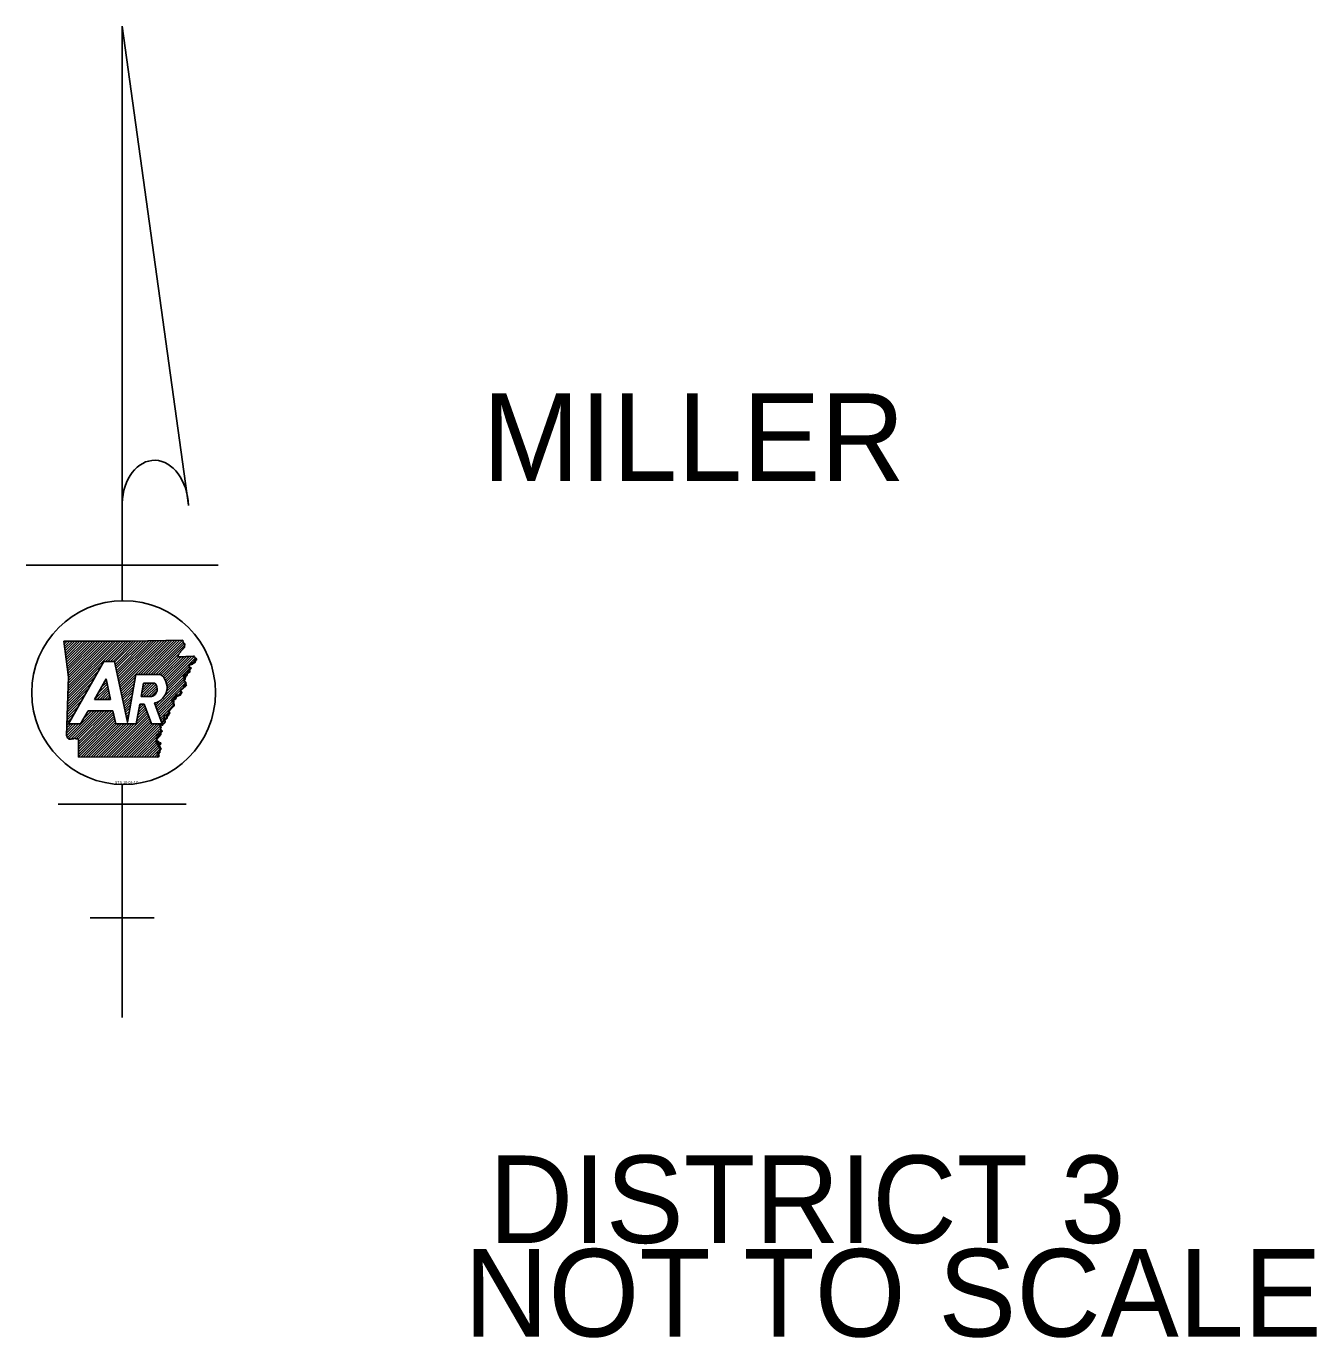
# Model space of a CAD drawing. Extents: x -35254 to 17396, y -8913 to 11592.
# Drawn here: x 11584 to 15125, y -5034 to -1436 of the extents above; entities that cross this region are included whole.
import ezdxf

# ---------------------------------------------------------------- set-up
doc = ezdxf.new("R2010")
doc.units = 0
doc.layers.add('2', color=7, linetype='Continuous')
doc.layers.add('R_Annotation', color=7, linetype='Continuous')

msp = doc.modelspace()

# ---------------------------------------------------------------- linework, layer by layer
at = {"layer": 'R_Annotation'}
for p, q in [((11847.3, -1436), (12029.1, -2750.1)), ((11847.3, -3011.9), (11847.3, -1436)), ((11584.1, -2914.4), (12110.4, -2914.4)), ((11687.6, -3124.7), (11689.8, -3122.6)), ((11688.4, -3130.9), (11696.8, -3122.6)), ((11689.2, -3137.1), (11703.7, -3122.6)), ((11689.9, -3143.3), (11710.7, -3122.6)), ((11690.7, -3149.5), (11717.6, -3122.6)), ((11691.5, -3155.7), (11724.6, -3122.6)), ((11692.3, -3161.9), (11731.6, -3122.6)), ((11693, -3168.1), (11738.5, -3122.6)), ((11693.8, -3174.3), (11745.5, -3122.6)), ((11694.6, -3180.5), (11752.5, -3122.6)), ((11695.3, -3186.7), (11759.4, -3122.6)), ((11696.1, -3192.9), (11766.4, -3122.6)), ((11696.9, -3199.1), (11773.3, -3122.6)), ((11697.7, -3205.3), (11780.3, -3122.6)), ((11697.9, -3274.7), (11850.1, -3122.5)), ((11698.1, -3267.5), (11843.1, -3122.5)), ((11698.4, -3260.3), (11836.1, -3122.5)), ((11698.4, -3211.5), (11787.3, -3122.6)), ((11698.6, -3253.1), (11829.2, -3122.5)), ((11698.8, -3245.9), (11822.2, -3122.5)), ((11699.1, -3238.7), (11815.2, -3122.6)), ((11699.2, -3217.7), (11794.3, -3122.6)), ((11699.3, -3231.5), (11808.2, -3122.6)), ((11699.6, -3224.3), (11801.2, -3122.6)), ((11801.3, -3178.2), (11857.1, -3122.5)), ((11808.3, -3178.2), (11864.1, -3122.5)), ((11815.3, -3178.2), (11871.1, -3122.4)), ((11822.2, -3178.2), (11878.2, -3122.3)), ((11826.6, -3180.8), (11885.2, -3122.2)), ((11827.8, -3186.6), (11892.3, -3122.1)), ((11829, -3192.3), (11899.4, -3122)), ((11830.3, -3198.1), (11906.5, -3121.9)), ((11831.5, -3203.8), (11913.5, -3121.7)), ((11832.7, -3209.5), (11920.6, -3121.6)), ((11833.9, -3215.3), (11927.7, -3121.5)), ((11835.2, -3221), (11934.8, -3121.4)), ((11836.4, -3226.7), (11941.8, -3121.3)), ((11837.6, -3232.5), (11948.9, -3121.2)), ((11838.8, -3238.2), (11956, -3121.1)), ((11840.1, -3244), (11963.1, -3121)), ((11841.3, -3249.7), (11970.2, -3120.8)), ((11842.5, -3255.4), (11977.3, -3120.7)), ((11890.9, -3214), (11984.4, -3120.5)), ((11897.9, -3214), (11991.6, -3120.3)), ((11904.9, -3214), (11998.7, -3120.2)), ((11911.8, -3214), (12005.8, -3120)), ((11918.8, -3214), (12012.9, -3119.8)), ((11925.7, -3214), (12014.5, -3125.3)), ((11932.7, -3214), (12017.9, -3128.9)), ((11939.7, -3214), (12018.8, -3134.9)), ((11946.6, -3214), (12002.9, -3157.8)), ((11956.8, -3217.8), (12008.8, -3165.8)), ((11960.2, -3221.4), (12016.2, -3165.4)), ((11963.2, -3225.3), (12023.5, -3165)), ((11965.8, -3229.7), (12030.9, -3164.6)), ((11967.9, -3234.6), (12038.2, -3164.2)), ((11969.5, -3239.9), (12044.8, -3164.6)), ((11697.7, -3281.9), (11791.6, -3187.9)), ((11700, -3349.8), (11797.1, -3178.2)), ((11797.1, -3178.2), (11826, -3178.2)), ((11953, -3214.6), (12001.5, -3166.1)), ((11969, -3261.3), (12032.3, -3198.1)), ((11970.4, -3245.9), (12048.1, -3168.3)), ((11970.5, -3252.9), (12031.5, -3191.9)), ((12045, -3178.4), (12051.3, -3172)), ((11696.9, -3303.5), (11764.4, -3236.1)), ((11697.2, -3296.3), (11773.5, -3220)), ((11697.4, -3289.1), (11782.6, -3204)), ((11771.4, -3282.5), (11803.2, -3226.3)), ((11789.2, -3251.1), (11805.1, -3235.2)), ((11798.3, -3235.1), (11803.9, -3229.5)), ((11843.8, -3261.2), (11883.3, -3221.6)), ((11845, -3266.9), (11881.8, -3230.1)), ((11884.6, -3214), (11952.1, -3214)), ((11940.3, -3304), (12017.5, -3226.8)), ((11942.2, -3309.1), (12018.8, -3232.4)), ((11963, -3274.3), (12016.2, -3221.1)), ((12024.5, -3212.8), (12033.1, -3204.2)), ((11696.5, -3317.9), (11746.2, -3268.2)), ((11696.7, -3310.7), (11755.3, -3252.1)), ((11771.8, -3282.5), (11807.6, -3246.7)), ((11778.7, -3282.5), (11808.8, -3252.4)), ((11780.1, -3267.2), (11806.3, -3240.9)), ((11785.7, -3282.5), (11810, -3258.1)), ((11792.7, -3282.5), (11811.3, -3263.9)), ((11799.6, -3282.5), (11812.5, -3269.6)), ((11846.2, -3272.6), (11880.3, -3238.5)), ((11847.4, -3278.4), (11878.9, -3247)), ((11848.7, -3284.1), (11877.4, -3255.4)), ((11849.9, -3289.9), (11875.9, -3263.8)), ((11851.1, -3295.6), (11874.5, -3272.3)), ((11899.3, -3274.9), (11935.9, -3238.2)), ((11900.7, -3266.5), (11929, -3238.2)), ((11902.2, -3258.1), (11922, -3238.2)), ((11903.7, -3249.6), (11915.1, -3238.2)), ((11905.1, -3241.2), (11908.1, -3238.2)), ((11905.6, -3238.2), (11937.3, -3238.2)), ((11906.3, -3274.9), (11939.8, -3241.3)), ((11913.2, -3274.9), (11942.2, -3245.9)), ((11920.2, -3274.9), (11943.5, -3251.6)), ((11927.2, -3274.9), (11942.9, -3259.2)), ((11944, -3314.1), (12020.1, -3238.1)), ((11945.9, -3319.2), (12021.4, -3243.7)), ((11997.6, -3274.5), (12007.4, -3264.7)), ((11696, -3332.3), (11728, -3300.3)), ((11696.2, -3325.1), (11737.1, -3284.3)), ((11771.4, -3282.5), (11815.2, -3282.5)), ((11806.6, -3282.5), (11813.7, -3275.4)), ((11813.6, -3282.5), (11814.9, -3281.1)), ((11852.4, -3301.3), (11873, -3280.7)), ((11853.6, -3307.1), (11871.5, -3289.1)), ((11854.8, -3312.8), (11870.1, -3297.6)), ((11856, -3318.6), (11868.6, -3306)), ((11890.3, -3326), (11911.1, -3305.3)), ((11891.8, -3317.6), (11909.2, -3300.2)), ((11893.3, -3309.2), (11907.2, -3295.2)), ((11894.8, -3300.7), (11900.2, -3295.2)), ((11907.4, -3295.2), (11895.7, -3295.2)), ((11899.3, -3274.9), (11928.2, -3274.9)), ((11927.6, -3349.8), (11907.4, -3295.2)), ((11936, -3292.3), (11957.2, -3349.8)), ((11936.5, -3293.8), (11938.6, -3291.7)), ((11938.4, -3298.9), (11951.6, -3285.6)), ((11947.8, -3324.3), (11989.6, -3282.5)), ((11949.7, -3329.4), (11988.8, -3290.3)), ((11951.5, -3334.5), (11988, -3298)), ((11695.5, -3346.7), (11709.8, -3332.4)), ((11695.7, -3339.5), (11718.9, -3316.4)), ((11697, -3387), (11770.2, -3313.8)), ((11701.1, -3389.8), (11777.2, -3313.8)), ((11706.2, -3391.8), (11784.2, -3313.8)), ((11714.4, -3390.5), (11791.1, -3313.8)), ((11721.5, -3390.4), (11798.1, -3313.8)), ((11727, -3391.9), (11805, -3313.8)), ((11727.2, -3405.6), (11819, -3313.8)), ((11727.2, -3398.6), (11812, -3313.8)), ((11727.2, -3412.5), (11822.6, -3317.1)), ((11727.2, -3419.5), (11823.9, -3322.8)), ((11727.3, -3426.4), (11825.1, -3328.6)), ((11727.3, -3433.4), (11826.3, -3334.3)), ((11727.4, -3440.2), (11827.6, -3340.1)), ((11753.7, -3313.8), (11733.3, -3349.8)), ((11734.4, -3440.2), (11828.8, -3345.8)), ((11741.2, -3335.9), (11763.3, -3313.8)), ((11750.3, -3319.8), (11756.3, -3313.8)), ((11821.9, -3313.8), (11753.7, -3313.8)), ((11796.9, -3440.3), (11916.7, -3320.5)), ((11803.9, -3440.4), (11918.6, -3325.6)), ((11810.8, -3440.4), (11920.5, -3330.7)), ((11817.8, -3440.4), (11922.4, -3335.8)), ((11824.8, -3440.4), (11924.3, -3340.9)), ((11857.3, -3324.3), (11867.1, -3314.4)), ((11858.5, -3330), (11865.6, -3322.9)), ((11859.7, -3335.8), (11864.2, -3331.3)), ((11860.9, -3341.5), (11862.7, -3339.7)), ((11887.4, -3342.9), (11914.9, -3315.4)), ((11888.9, -3334.5), (11913, -3310.4)), ((11953.4, -3339.6), (11974.8, -3318.2)), ((11955.3, -3344.7), (11971.8, -3328.2)), ((11694.4, -3382.7), (11727.2, -3349.8)), ((11694.5, -3375.6), (11720.3, -3349.8)), ((11694.8, -3368.4), (11713.3, -3349.8)), ((11695, -3361.1), (11706.3, -3349.8)), ((11695.3, -3353.9), (11700.7, -3348.5)), ((11733.3, -3349.8), (11700, -3349.8)), ((11741.3, -3440.2), (11831.7, -3349.8)), ((11748.3, -3440.3), (11838.7, -3349.8)), ((11755.2, -3440.3), (11845.7, -3349.8)), ((11762.2, -3440.3), (11852.6, -3349.8)), ((11769.1, -3440.3), (11859.6, -3349.8)), ((11776.1, -3440.3), (11866.6, -3349.8)), ((11783, -3440.3), (11873.5, -3349.8)), ((11790, -3440.3), (11880.5, -3349.8)), ((11886.2, -3349.8), (11829.6, -3349.8)), ((11831.7, -3440.4), (11926.1, -3346)), ((11838.7, -3440.4), (11929.3, -3349.8)), ((11845.6, -3440.4), (11936.2, -3349.8)), ((11852.6, -3440.4), (11943.2, -3349.8)), ((11859.5, -3440.4), (11950.2, -3349.8)), ((11866.5, -3440.5), (11952.5, -3354.5)), ((11873.4, -3440.5), (11952.8, -3361.1)), ((11880.4, -3440.5), (11953.1, -3367.8)), ((11887.3, -3440.5), (11953.4, -3374.4)), ((11957.2, -3349.8), (11927.6, -3349.8)), ((11894.3, -3440.5), (11942, -3392.8)), ((11901.3, -3440.5), (11944.1, -3397.6)), ((11908.2, -3440.5), (11946.3, -3402.5)), ((11915.2, -3440.5), (11948.4, -3407.3)), ((11922.1, -3440.5), (11950.6, -3412.1)), ((11929.1, -3440.6), (11952.4, -3417.3)), ((11936, -3440.6), (11949.2, -3427.4)), ((11943, -3440.6), (11946.1, -3437.5)), ((11847.3, -4155.5), (11847.3, -3516)), ((11671.8, -3570.3), (12022.7, -3570.3)), ((11759.5, -3881.9), (11935, -3881.9))]:
    msp.add_line(p, q, dxfattribs=at)
for points in [[(11687.3, -3122.6), (11783.4, -3122.6), (11867.8, -3122.4), (11967.3, -3120.9), (12013.4, -3119.8)], [(11698, -3272), (11699.7, -3221.3), (11687.3, -3122.6)], [(11687.4, -3122.6), (11783.5, -3122.6), (11867.8, -3122.5), (11967.3, -3120.9), (12013.4, -3119.8)], [(11694.3, -3382.6), (11699.7, -3221.3), (11687.4, -3122.6)], [(12043.6, -3164), (12051.9, -3172.7), (12031.2, -3189.7), (12033.4, -3206.9), (12015.6, -3218.6), (12021.7, -3245.1), (12008, -3257.6), (12006.8, -3271.2), (11990.1, -3277.2), (11987.5, -3302.9), (11975.5, -3315.7), (11969.8, -3335), (11952.3, -3351), (11953.6, -3379.1), (11941.8, -3392.4), (11952.6, -3416.6), (11945.1, -3440.6)], [(11999.1, -3166.2), (12044.2, -3163.9)], [(11999.1, -3166.3), (12044.2, -3163.9)], [(11826, -3178.2), (11861.7, -3345.2), (11884.6, -3214)], [(11803.2, -3226.3), (11815.2, -3282.5)], [(11694.3, -3382.6), (11698, -3272)], [(11899.3, -3274.9), (11905.6, -3238.2)], [(11895.7, -3295.2), (11886.2, -3349.8)], [(11829.6, -3349.8), (11821.9, -3313.8)], [(11945.1, -3440.6), (11727.3, -3440.2), (11727.2, -3392.1)], [(11945.1, -3440.6), (11727.3, -3440.2), (11727.2, -3392.1)]]:
    msp.add_lwpolyline(points, dxfattribs=at)
for centre, major_axis, ratio, start_param, end_param in [((11938.1, -2753), (-3.9, 126.3), 0.719778, 4.712385, 7.768526), ((11927, -3249.7), (-43.6, 0), 0.999987, 1.777838, 4.099264), ((11921.3, -3253.7), (-22.3, 0), 0.999987, 1.887169, 3.90762)]:
    msp.add_ellipse(centre, major_axis=major_axis, ratio=ratio, start_param=start_param, end_param=end_param, dxfattribs=at)
msp.add_ellipse((11851.4, -3263.9), major_axis=(252.1, 0), ratio=0.999976, dxfattribs=at)
for points in [[(12013.4, -3119.8), (12013.7, -3122.4), (12014.5, -3123.8), (12014.6, -3126.3), (12015.7, -3127.4), (12017.4, -3128.5), (12018.9, -3130.2), (12019.3, -3132.2), (12018.8, -3134.3), (12018.7, -3136.6), (12018.5, -3138.6), (12018.1, -3140.4), (12016.7, -3142), (12015.3, -3143), (12014.1, -3144.2), (12013.2, -3145.6), (12011.6, -3147), (12010.1, -3148.5), (12008.8, -3149.8), (12007.6, -3151.5), (12007, -3153.3), (12005.6, -3154.6), (12004.5, -3155.8), (12003.1, -3157.4), (12002.4, -3159), (12001.1, -3160.8), (12000.7, -3162.6), (11999.9, -3164), (11999.8, -3164.3)], [(12013.4, -3119.8), (12013.7, -3122.5), (12014.5, -3123.8), (12014.6, -3126.3), (12015.7, -3127.4), (12017.4, -3128.5), (12018.9, -3130.2), (12019.3, -3132.2), (12018.8, -3134.3), (12018.7, -3136.6), (12018.4, -3138.6), (12018.1, -3140.5), (12016.7, -3141.9), (12015.3, -3143), (12014, -3144.3), (12013.2, -3145.6), (12011.6, -3147), (12010.1, -3148.5), (12008.8, -3149.8), (12007.6, -3151.5), (12007, -3153.3), (12005.6, -3154.6), (12004.5, -3155.8), (12003.1, -3157.4), (12002.4, -3159), (12001, -3160.8), (12000.7, -3162.6), (11999.8, -3164.1), (11999.8, -3164.3)], [(12043.6, -3164), (12044.2, -3163.9), (12046.2, -3166.1), (12047.1, -3167.9), (12048.5, -3168.9), (12050, -3169.4), (12051.1, -3170.8), (12051.8, -3172.3), (12051.4, -3173.6), (12049.7, -3173.7), (12047.9, -3174), (12046.1, -3173.9), (12044.7, -3175.1), (12046, -3176.7), (12047.7, -3178.2), (12048.2, -3179.8), (12047.3, -3181.3), (12045.4, -3182.2), (12043.5, -3182.9), (12041.9, -3184.3), (12041.1, -3185.7), (12039.2, -3186.3), (12037.3, -3186.8), (12035.7, -3187), (12033.8, -3187.4), (12032, -3188.3), (12031.2, -3189.8), (12031.4, -3192), (12031.4, -3194.3), (12033.3, -3195.1), (12035, -3195.2), (12036.7, -3196), (12036.5, -3197.3), (12035.3, -3199), (12033.8, -3200.3), (12032.3, -3200.9), (12030.9, -3202.2), (12031.4, -3203.5), (12032.6, -3204.3), (12033.5, -3205.6), (12033.4, -3206.9), (12032, -3207.8), (12030.4, -3207.4), (12029.3, -3205.9), (12028, -3205.5), (12026.9, -3204.9), (12025.6, -3205.7), (12025.6, -3207.4), (12025.1, -3209.3), (12025.5, -3210.6), (12026, -3212.5), (12026, -3214), (12025.5, -3216), (12024.5, -3218.1), (12023.4, -3218.7), (12022.8, -3216.5), (12022.6, -3214.6), (12021.9, -3213.5), (12020.9, -3213.5), (12019.7, -3214.4), (12018.3, -3215.8), (12016.6, -3217.3), (12015.6, -3218.7), (12016.1, -3220.6), (12017.4, -3221), (12018.5, -3220.7), (12019, -3219.5), (12019.9, -3219.3), (12020.9, -3221.2)], [(12020.9, -3221.2), (12021.2, -3222.9), (12020.2, -3224.7), (12019.8, -3226.5), (12019.9, -3228.4), (12018.1, -3229.4), (12016.4, -3230.6), (12017.4, -3232), (12019.2, -3233.3), (12020.9, -3234.3), (12022, -3235.4), (12022.3, -3237.8), (12022.7, -3239.4), (12023.3, -3241.5), (12023.5, -3243), (12022.4, -3244.7), (12021.2, -3245.1), (12019.8, -3244.7), (12018.3, -3244.6), (12017.1, -3245.7), (12016.2, -3247.4), (12015.3, -3249.1), (12014.6, -3250.5), (12014, -3252.1), (12012.7, -3253.9), (12011.1, -3254.1), (12009.2, -3254.6), (12008, -3255.9), (12008.2, -3258.1), (12009.3, -3259.6), (12010.1, -3261.4), (12010.7, -3263), (12010.4, -3265.1), (12009.6, -3266.6), (12008.5, -3267.5), (12008, -3269.3), (12007.3, -3270.8), (12006.6, -3271.3), (12005.1, -3271.1), (12003.6, -3270.9), (12002.3, -3271), (12001.1, -3271.6), (11999.8, -3271.2), (11998.5, -3269.8), (11997.4, -3268.7), (11996.2, -3268.3), (11995, -3268.9), (11994.8, -3270.9), (11995.4, -3272.9), (11995.9, -3275.6), (11995.4, -3277.3), (11995.1, -3280.1)], [(11995.1, -3280.1), (11993.1, -3281.6), (11992.1, -3283.3), (11986.8, -3282.8), (11987, -3284.7), (11985.1, -3285.6), (11983.4, -3286.9), (11984.4, -3288.3), (11986.2, -3289.6), (11988, -3290.6), (11989.1, -3291.6), (11989.4, -3294.1), (11989.7, -3295.6), (11990.3, -3297.8), (11990.5, -3299.2), (11989.4, -3301), (11988.2, -3301.4), (11986.9, -3300.9), (11985.4, -3300.8), (11984.1, -3302), (11983.2, -3303.7), (11982.3, -3305.4), (11981.7, -3306.8), (11981, -3308.3), (11979.7, -3310.1), (11978.1, -3310.4), (11976.2, -3310.9), (11975.1, -3312.1), (11975.3, -3314.4), (11976.3, -3315.8), (11977.2, -3317.7), (11977.7, -3319.3), (11977.5, -3321.3), (11976.7, -3322.8), (11975.6, -3323.7), (11975.1, -3325.6), (11974.3, -3327.1), (11973.6, -3327.5), (11972.2, -3327.4), (11970.6, -3327.1), (11969.3, -3327.2), (11968.1, -3327.9), (11966.8, -3327.4), (11965.5, -3326), (11964.4, -3324.9), (11963.2, -3324.5), (11962, -3325.2), (11961.8, -3327.2), (11962.4, -3329.1), (11962.9, -3331.9), (11962.4, -3333.5), (11962.2, -3336.3)], [(11962.2, -3336.3), (11962, -3336.4), (11961, -3337.7), (11961.6, -3339.9), (11963.9, -3340.7), (11965, -3342.7), (11965, -3344.5), (11964.3, -3346.9), (11963.2, -3348.1), (11961.1, -3348.5), (11959.5, -3348.8), (11959.3, -3351.5), (11958.5, -3352.9), (11957.3, -3353.3), (11955.5, -3352.4), (11954.4, -3352), (11953.1, -3351.4), (11951.5, -3350.5), (11950.2, -3350.6), (11950.6, -3353.2), (11950.7, -3353.3), (11952.1, -3355.3), (11953.5, -3356.8), (11954.2, -3358.7)], [(11962.2, -3336.3), (11962, -3336.4), (11961, -3337.7), (11961.6, -3339.9), (11963.9, -3340.7), (11965, -3342.7), (11965, -3344.5), (11964.3, -3346.9), (11963.2, -3348.1), (11961.1, -3348.5), (11959.5, -3348.8), (11959.3, -3351.5), (11958.5, -3352.9), (11957.3, -3353.3), (11955.5, -3352.4), (11954.4, -3352), (11953.1, -3351.4), (11951.5, -3350.5), (11950.2, -3350.6), (11950.6, -3353.2), (11950.7, -3353.3), (11952.1, -3355.3), (11953.5, -3356.8), (11954.2, -3358.7)], [(11954.2, -3358.7), (11953.6, -3360.1), (11952.9, -3362.4), (11953.1, -3364.4), (11954, -3366.2), (11955.4, -3367.1), (11957, -3368.5), (11956.9, -3370.6), (11956, -3371.3), (11953.9, -3370.8), (11952.3, -3370.1), (11950.9, -3370.5), (11949.1, -3371.4), (11947.7, -3371.6), (11947.8, -3374.5), (11949.6, -3376.5), (11951.2, -3376.5), (11953.1, -3376.7), (11953.7, -3378.8), (11952.6, -3380.6), (11950.9, -3381.5), (11948.6, -3380.4), (11947, -3379.3), (11945.4, -3378.2), (11943.4, -3377.7), (11942.2, -3377.9), (11941.7, -3380.4), (11942.7, -3382.7), (11944.2, -3384.3), (11945.6, -3386.3), (11945.4, -3387.8), (11944.3, -3388.2), (11942.4, -3388.6), (11941.3, -3389.2), (11941, -3389.6), (11941.6, -3391.7), (11942.1, -3393.8), (11942.1, -3395.6), (11941.5, -3397), (11940.5, -3399.4), (11940.6, -3401), (11941.3, -3401.7), (11942.2, -3401.5), (11943.4, -3400.7), (11944.2, -3399.7), (11944.8, -3398.5), (11946, -3397.5), (11947.6, -3398.4), (11948, -3400.2), (11947.1, -3401.8), (11945.8, -3402.6), (11944.3, -3403.2), (11943.1, -3404.4), (11943.4, -3406), (11944.3, -3406.8), (11946.6, -3406.4), (11948, -3405.7), (11948.9, -3405), (11949.9, -3403.9), (11950.4, -3402.9), (11951.2, -3401.8), (11952.6, -3401.5), (11953.2, -3402.4), (11952.9, -3404.4), (11952.1, -3406.4), (11951, -3407.9), (11949.7, -3409.1), (11948.2, -3411.5), (11948.5, -3413.8), (11949.1, -3415.7), (11949.9, -3417), (11951.3, -3416.8), (11952.9, -3416.6), (11953.9, -3417.3), (11953.8, -3419), (11952.6, -3420.7), (11951.5, -3422.2), (11950.9, -3424.3), (11951.1, -3425.8), (11951.1, -3427.1), (11950.6, -3428.7), (11949.8, -3429.5), (11947.6, -3429.4), (11945.3, -3429.2), (11944.1, -3429.9), (11944.3, -3431.9), (11945.6, -3433.4), (11946.6, -3434.2), (11948, -3435.8), (11948.5, -3437.2), (11948.4, -3438.4), (11947.5, -3439.4), (11945.1, -3440.6)], [(11954.2, -3358.7), (11953.6, -3360.1), (11952.9, -3362.4), (11953.1, -3364.4), (11954, -3366.2), (11955.4, -3367.1), (11957, -3368.5), (11956.9, -3370.6), (11956, -3371.3), (11953.9, -3370.8), (11952.3, -3370.1), (11950.9, -3370.5), (11949.1, -3371.4), (11947.7, -3371.6), (11947.8, -3374.5), (11949.6, -3376.5), (11951.2, -3376.5), (11953.1, -3376.7), (11953.7, -3378.8), (11952.6, -3380.6), (11950.9, -3381.5), (11948.6, -3380.4), (11947, -3379.3), (11945.4, -3378.2), (11943.4, -3377.7), (11942.2, -3377.9), (11941.7, -3380.4), (11942.7, -3382.7), (11944.2, -3384.3), (11945.6, -3386.3), (11945.4, -3387.8), (11944.3, -3388.2), (11942.4, -3388.6), (11941.3, -3389.2), (11941, -3389.6), (11941.6, -3391.7), (11942.1, -3393.8), (11942.1, -3395.6), (11941.5, -3397), (11940.5, -3399.4), (11940.6, -3401), (11941.3, -3401.7), (11942.2, -3401.5), (11943.4, -3400.7), (11944.2, -3399.7), (11944.8, -3398.5), (11946, -3397.5), (11947.6, -3398.4), (11948, -3400.2), (11947.1, -3401.8), (11945.8, -3402.6), (11944.3, -3403.2), (11943.1, -3404.4), (11943.4, -3406), (11944.3, -3406.8), (11946.6, -3406.4), (11948, -3405.7), (11948.9, -3405), (11949.9, -3403.9), (11950.4, -3402.9), (11951.2, -3401.8), (11952.6, -3401.5), (11953.2, -3402.4), (11952.9, -3404.4), (11952.1, -3406.4), (11951, -3407.9), (11949.7, -3409.1), (11948.2, -3411.5), (11948.5, -3413.8), (11949.1, -3415.7), (11949.9, -3417), (11951.3, -3416.8), (11952.9, -3416.6), (11953.9, -3417.3), (11953.8, -3419), (11952.6, -3420.7), (11951.5, -3422.2), (11950.9, -3424.3), (11951.1, -3425.8), (11951.1, -3427.1), (11950.6, -3428.7), (11949.8, -3429.5), (11947.6, -3429.4), (11945.3, -3429.2), (11944.1, -3429.9), (11944.3, -3431.9), (11945.6, -3433.4), (11946.6, -3434.2), (11948, -3435.8), (11948.5, -3437.2), (11948.4, -3438.4), (11947.5, -3439.4), (11945.1, -3440.6)], [(11727.2, -3392.1), (11727.4, -3392.3), (11726.3, -3391.5), (11724.7, -3390.7), (11723, -3390.6), (11720.8, -3390.3), (11719, -3390.1), (11717.1, -3388.9), (11715.1, -3390.2), (11712.8, -3391.1), (11711.5, -3390), (11709.8, -3390.8), (11708.6, -3390.4), (11706.5, -3391.9), (11704.5, -3391.3), (11703.1, -3391.7), (11701.3, -3391.7), (11701, -3389.6), (11699.2, -3389.4), (11697.7, -3388.5), (11696.8, -3386.5), (11696, -3384.8), (11694.3, -3382.6)], [(11727.2, -3392.1), (11727.4, -3392.3), (11726.3, -3391.5), (11724.7, -3390.7), (11723, -3390.6), (11720.8, -3390.3), (11719, -3390.1), (11717.1, -3388.9), (11715.1, -3390.2), (11712.8, -3391.1), (11711.5, -3390.1), (11709.8, -3390.8), (11708.6, -3390.4), (11706.5, -3391.8), (11704.5, -3391.3), (11703.1, -3391.7), (11701.3, -3391.7), (11701, -3389.6), (11699.2, -3389.4), (11697.8, -3388.5), (11696.7, -3386.4), (11696, -3384.8), (11694.3, -3382.6)]]:
    msp.add_spline(points, degree=3, dxfattribs=at)

# ---------------------------------------------------------------- texts
at = {"layer": '2'}
for s, p in [('MILLER', (12835.5, -2683.3)), ('NOT TO SCALE', (12785, -5030.2))]:
    msp.add_text(s, height=240, dxfattribs=at).set_placement(p)
at = {"layer": 'R_Annotation'}
for s, height, p in [('STS 10-03-17', 7.288, (11827.3, -3513.9)), ('DISTRICT 3', 240, (12853.2, -4773.6))]:
    msp.add_text(s, height=height, dxfattribs=at).set_placement(p)

doc.saveas('drawing.dxf')
